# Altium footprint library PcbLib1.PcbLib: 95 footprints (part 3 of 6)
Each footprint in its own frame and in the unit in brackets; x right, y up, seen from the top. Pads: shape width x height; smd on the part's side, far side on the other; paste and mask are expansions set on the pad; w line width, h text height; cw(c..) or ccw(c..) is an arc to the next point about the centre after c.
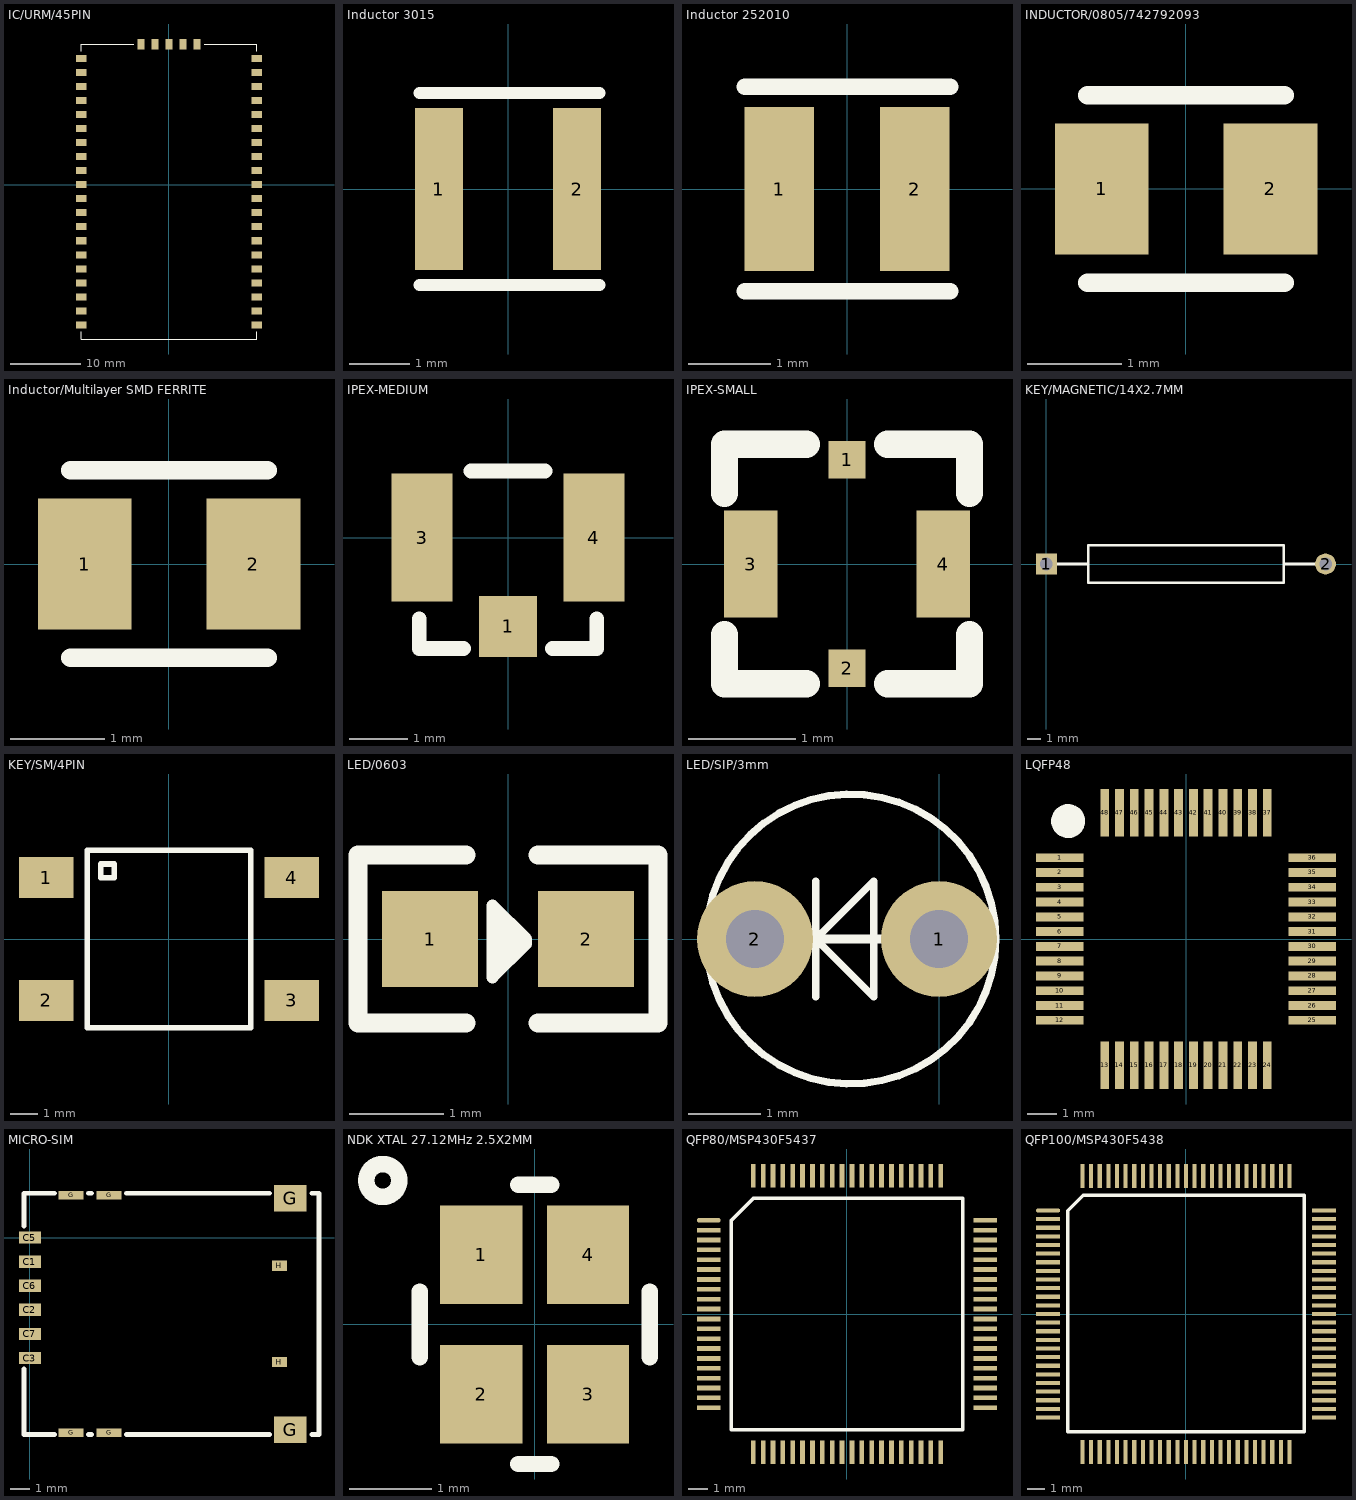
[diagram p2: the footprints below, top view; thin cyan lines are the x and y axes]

## IC/URM/45PIN [mm]
pads (45):
  rect 1.5x1 smd: 1(-12.5,18) 2(-12.5,16) 3(-12.5,14) 4(-12.5,12) 5(-12.5,10) 6(-12.5,8) 7(-12.5,6) 8(-12.5,4) 9(-12.5,2) 10(-12.5,0) 11(-12.5,-2) 12(-12.5,-4) 13(-12.5,-6) 14(-12.5,-8) 15(-12.5,-10) 16(-12.5,-12) 17(-12.5,-14) 18(-12.5,-16) 19(-12.5,-18) 20(-12.5,-20) 21(12.5,-20) 22(12.5,-18) 23(12.5,-16) 24(12.5,-14) 25(12.5,-12) 26(12.5,-10) 27(12.5,-8) 28(12.5,-6) 29(12.5,-4) 30(12.5,-2) 31(12.5,0) 32(12.5,2) 33(12.5,4) 34(12.5,6) 35(12.5,8) 36(12.5,10) 37(12.5,12) 38(12.5,14) 39(12.5,16) 40(12.5,18)
  rect 1x1.5 smd: 41(-4,20) 42(-2,20) 43(0,20) 44(2,20) 45(4,20)
Top Overlay:
  lines w0.127: -12.5,-21 -12.5,-22 12.5,-22 12.5,-21 ; -12.5,19 -12.5,20 -5,20 ; 5,20 12.5,20 12.5,19

## Inductor 3015 [mm]
pads (2):
  rect 0.8x2.7 smd: 1(-1.15,0) 2(1.15,0)
Top Overlay:
  lines w0.2: -1.473,-1.6 1.527,-1.6 ; -1.473,1.6 1.527,1.6

## Inductor 252010 [mm]
pads (2):
  rect 0.85x2 smd: 1(-0.825,0) 2(0.825,0)
Top Overlay:
  lines w0.2: -1.245,-1.245 1.255,-1.245 ; -1.245,1.245 1.255,1.245

## INDUCTOR/0805/742792093 [mm]
pads (2):
  rect 1x1.4 smd paste+0 mask+0.1: 1(-0.9,0) 2(0.9,0)
Top Overlay:
  lines w0.2: -1.05,-1 1.05,-1 ; -1.05,1 1.05,1

## Inductor/Multilayer SMD FERRITE [mm]
pads (2):
  rect 1x1.4 smd paste+0 mask+0.1: 1(-0.9,0) 2(0.9,0)
Top Overlay:
  lines w0.2: -1.05,-1 1.05,-1 ; -1.05,1 1.05,1

## IPEX-MEDIUM [mm]
pads (3):
  rect 1x1.05 smd: 1(0,-1.525)
  rect 1.05x2.2 smd: 3(-1.475,0) 4(1.475,0)
Top Overlay:
  lines w0.254: -1.524,-1.397 -1.524,-1.905 -0.762,-1.905 ; -0.635,1.143 0.635,1.143 ; 0.762,-1.905 1.524,-1.905 1.524,-1.397

## IPEX-SMALL [mm]
pads (4):
  rect 0.35x0.35 smd: 1(0,0.975) 2(0,-0.975)
  rect 0.5x1 smd: 3(-0.9,0) 4(0.9,0)
Top Overlay:
  lines w0.254: -1.143,-0.66 -1.143,-1.118 -0.381,-1.118 ; -1.143,0.66 -1.143,1.118 -0.381,1.118 ; 0.381,-1.118 1.143,-1.118 1.143,-0.66 ; 0.381,1.118 1.143,1.118 1.143,0.66

## KEY/MAGNETIC/14X2.7MM [mm]
pads (2):
  rect 1.5x1.5 hole 0.9: 1(0,0)
  round 1.5 hole 0.9: 2(20,0)
Top Overlay:
  lines w0.2: 0,0 3,0 ; 20,0 17,0 ; 3,0 3,-1.35 17,-1.35 17,0 ; 3,0 3,1.35 17,1.35 17,0

## KEY/SM/4PIN [mm]
pads (4):
  rect 2x1.5 smd: 1(-4.5,2.25) 2(-4.5,-2.25) 3(4.5,-2.25) 4(4.5,2.25)
Top Overlay:
  lines w0.203: -3,-3.25 -3,3.25 3,3.25 3,-3.25 -3,-3.25 ; -2.5,2.25 -2,2.25 -2,2.75 -2.5,2.75 -2.5,2.25

## LED/0603 [mil]
pads (2):
  rect 40x40 smd: 1(-32.5,0) 2(32.5,0)
Top Overlay:
  lines w5: -3.5,-8 -3.5,11 -6.5,14 ; -0.5,-5 -0.5,3 ; -0.5,-3 2.5,0 7.5,0 ; -6.5,14 7.5,0 ; -6.5,14 -6.5,-16 7.5,-2 7.5,0
  lines w8: -17.5,-35 -62.5,-35 -62.5,35 -17.5,35 ; 12.5,-35 62.5,-35 62.5,35 12.5,35

## LED/SIP/3mm [mm]
pads (2):
  round 1.6 hole 0.8: 1(0,0) 2(-2.54,0)
Top Overlay:
  circle w0.1: c-1.216,0 r2
  lines w0.1: -1.7,-0.8 -1.7,0 ; -1.7,0.8 -1.7,0 ; -1.7,0 -0.9,0.8 -0.9,-0.8 -1.7,0
  lines w0.127: -1.7,0 -0.686,0

## LQFP48 [mm]
pads (48):
  rect 1.6x0.3 smd paste+0 mask+0.04: 1(-4.275,2.75) 2(-4.275,2.25) 3(-4.275,1.75) 4(-4.275,1.25) 5(-4.275,0.75) 6(-4.275,0.25) 7(-4.275,-0.25) 8(-4.275,-0.75) 9(-4.275,-1.25) 10(-4.275,-1.75) 11(-4.275,-2.25) 12(-4.275,-2.75) 25(4.275,-2.75) 26(4.275,-2.25) 27(4.275,-1.75) 28(4.275,-1.25) 29(4.275,-0.75) 30(4.275,-0.25) 31(4.275,0.25) 32(4.275,0.75) 33(4.275,1.25) 34(4.275,1.75) 35(4.275,2.25) 36(4.275,2.75)
  rect 0.3x1.6 smd paste+0 mask+0.04: 13(-2.75,-4.275) 14(-2.25,-4.275) 15(-1.75,-4.275) 16(-1.25,-4.275) 17(-0.75,-4.275) 18(-0.25,-4.275) 19(0.25,-4.275) 20(0.75,-4.275) 21(1.25,-4.275) 22(1.75,-4.275) 23(2.25,-4.275) 24(2.75,-4.275) 37(2.75,4.275) 38(2.25,4.275) 39(1.75,4.275) 40(1.25,4.275) 41(0.75,4.275) 42(0.25,4.275) 43(-0.25,4.275) 44(-0.75,4.275) 45(-1.25,4.275) 46(-1.75,4.275) 47(-2.25,4.275) 48(-2.75,4.275)
Top Overlay:
  circle w0.6: c-3.988,3.988 r0.274

## MICRO-SIM [mm]
pads (14):
  rect 1.15x0.65 smd: C1(0,-1.27) C2(0,-3.81) C3(0,-6.35) C5(0,0) C6(0,-2.54) C7(0,-5.08)
  rect 1.3x0.45 smd: G(2.17,-10.295) G(2.17,2.235) G(4.17,-10.295) G(4.17,2.235)
  rect 1.7x1.4 smd: G(13.73,-10.135) G(13.73,2.075)
  rect 0.8x0.54 smd: H(13.15,-6.565) H(13.15,-1.485)
Top Overlay:
  lines w0.254: -0.305,-6.934 -0.305,-10.389 1.295,-10.389 ; -0.305,0.61 -0.305,2.337 1.295,2.337 ; 3.073,2.337 3.251,2.337 ; 3.086,-10.389 3.264,-10.389 ; 5.08,-10.389 12.624,-10.389 ; 5.08,2.337 12.624,2.337 ; 14.859,-10.389 15.24,-10.389 15.24,2.337 14.859,2.337

## NDK XTAL 27.12MHz 2.5X2MM [mm]
pads (4):
  rect 1x1.2 smd paste+0 mask+0.1: 1(-0.65,0.85) 3(0.65,-0.85) 4(0.65,0.85)
  rect 1x1.2 smd mask+0.1: 2(-0.65,-0.85)
Top Overlay:
  lines w0.2: -1.4,-0.4 -1.4,0.4 ; -0.2,-1.7 0.2,-1.7 ; -0.2,1.7 0.2,1.7 ; 1.4,-0.4 1.4,0.4 ; -2.049,1.752 -2.049,1.766 -2.047,1.78 -2.045,1.794 -2.041,1.808 -2.037,1.821 -2.032,1.834 -2.026,1.846 -2.019,1.858 -2.011,1.87 -2.002,1.881 -1.993,1.891 -1.983,1.901 -1.972,1.91 -1.961,1.918 -1.949,1.926 -1.937,1.932 -1.924,1.938 -1.911,1.943 -1.898,1.947 -1.884,1.949 -1.87,1.951 -1.856,1.952 -1.842,1.952 -1.828,1.951 -1.814,1.949 -1.801,1.947 -1.787,1.943 -1.774,1.938 -1.761,1.932 -1.749,1.926 -1.737,1.918 -1.726,1.91 -1.715,1.901 -1.705,1.891 -1.696,1.881 -1.687,1.87 -1.68,1.858 -1.673,1.846 -1.666,1.834 -1.661,1.821 -1.657,1.808 -1.654,1.794 -1.651,1.78 -1.65,1.766 -1.649,1.752 -1.65,1.738 -1.651,1.725 -1.654,1.711 -1.657,1.697 -1.661,1.684 -1.666,1.671 -1.673,1.659 -1.68,1.646 -1.687,1.635 -1.696,1.624 -1.705,1.614 -1.715,1.604 -1.726,1.595 -1.737,1.587 -1.749,1.579 -1.761,1.573 -1.774,1.567 -1.787,1.562 -1.801,1.558 -1.814,1.555 -1.828,1.554 -1.842,1.553 -1.856,1.553 -1.87,1.554 -1.884,1.555 -1.898,1.558 -1.911,1.562 -1.924,1.567 -1.937,1.573 -1.949,1.579 -1.961,1.587 -1.972,1.595 -1.983,1.604 -1.993,1.614 -2.002,1.624 -2.011,1.635 -2.019,1.646 -2.026,1.659 -2.032,1.671 -2.037,1.684 -2.041,1.697 -2.045,1.711 -2.047,1.725 -2.049,1.738 -2.049,1.752

## QFP80/MSP430F5437 [mm]
pads (80):
  oval 1.2x0.24 smd: 1(-7,4.75)
  rect 1.2x0.24 smd: 2(-7,4.25) 3(-7,3.75) 4(-7,3.25) 5(-7,2.75) 6(-7,2.25) 7(-7,1.75) 8(-7,1.25) 9(-7,0.75) 10(-7,0.25) 11(-7,-0.25) 12(-7,-0.75) 13(-7,-1.25) 14(-7,-1.75) 15(-7,-2.25) 16(-7,-2.75) 17(-7,-3.25) 18(-7,-3.75) 19(-7,-4.25) 20(-7,-4.75) 41(7,-4.75) 42(7,-4.25) 43(7,-3.75) 44(7,-3.25) 45(7,-2.75) 46(7,-2.25) 47(7,-1.75) 48(7,-1.25) 49(7,-0.75) 50(7,-0.25) 51(7,0.25) 52(7,0.75) 53(7,1.25) 54(7,1.75) 55(7,2.25) 56(7,2.75) 57(7,3.25) 58(7,3.75) 59(7,4.25) 60(7,4.75)
  rect 0.24x1.2 smd: 21(-4.75,-7) 22(-4.25,-7) 23(-3.75,-7) 24(-3.25,-7) 25(-2.75,-7) 26(-2.25,-7) 27(-1.75,-7) 28(-1.25,-7) 29(-0.75,-7) 30(-0.25,-7) 31(0.25,-7) 32(0.75,-7) 33(1.25,-7) 34(1.75,-7) 35(2.25,-7) 36(2.75,-7) 37(3.25,-7) 38(3.75,-7) 39(4.25,-7) 40(4.75,-7) 61(4.75,7) 62(4.25,7) 63(3.75,7) 64(3.25,7) 65(2.75,7) 66(2.25,7) 67(1.75,7) 68(1.25,7) 69(0.75,7) 70(0.25,7) 71(-0.25,7) 72(-0.75,7) 73(-1.25,7) 74(-1.75,7) 75(-2.25,7) 76(-2.75,7) 77(-3.25,7) 78(-3.75,7) 79(-4.25,7) 80(-4.75,7)
Top Overlay:
  lines w0.2: -5.865,-5.865 -5.865,4.73 -4.73,5.865 5.865,5.865 5.865,-5.865 -5.865,-5.865

## QFP100/MSP430F5438 [mm]
pads (100):
  oval 1.4x0.24 smd: 1(-8,6)
  rect 1.4x0.24 smd: 2(-8,5.5) 3(-8,5) 4(-8,4.5) 5(-8,4) 6(-8,3.5) 7(-8,3) 8(-8,2.5) 9(-8,2) 10(-8,1.5) 11(-8,1) 12(-8,0.5) 13(-8,0) 14(-8,-0.5) 15(-8,-1) 16(-8,-1.5) 17(-8,-2) 18(-8,-2.5) 19(-8,-3) 20(-8,-3.5) 21(-8,-4) 22(-8,-4.5) 23(-8,-5) 24(-8,-5.5) 25(-8,-6) 51(8,-6) 52(8,-5.5) 53(8,-5) 54(8,-4.5) 55(8,-4) 56(8,-3.5) 57(8,-3) 58(8,-2.5) 59(8,-2) 60(8,-1.5) 61(8,-1) 62(8,-0.5) 63(8,0) 64(8,0.5) 65(8,1) 66(8,1.5) 67(8,2) 68(8,2.5) 69(8,3) 70(8,3.5) 71(8,4) 72(8,4.5) 73(8,5) 74(8,5.5) 75(8,6)
  rect 0.24x1.4 smd: 26(-6,-8) 27(-5.5,-8) 28(-5,-8) 29(-4.5,-8) 30(-4,-8) 31(-3.5,-8) 32(-3,-8) 33(-2.5,-8) 34(-2,-8) 35(-1.5,-8) 36(-1,-8) 37(-0.5,-8) 38(0,-8) 39(0.5,-8) 40(1,-8) 41(1.5,-8) 42(2,-8) 43(2.5,-8) 44(3,-8) 45(3.5,-8) 46(4,-8) 47(4.5,-8) 48(5,-8) 49(5.5,-8) 50(6,-8) 76(6,8) 77(5.5,8) 78(5,8) 79(4.5,8) 80(4,8) 81(3.5,8) 82(3,8) 83(2.5,8) 84(2,8) 85(1.5,8) 86(1,8) 87(0.5,8) 88(0,8) 89(-0.5,8) 90(-1,8) 91(-1.5,8) 92(-2,8) 93(-2.5,8) 94(-3,8) 95(-3.5,8) 96(-4,8) 97(-4.5,8) 98(-5,8) 99(-5.5,8) 100(-6,8)
Top Overlay:
  lines w0.2: -6.857,-6.827 -6.857,6 -5.968,6.889 6.859,6.889 6.859,-6.827 -6.857,-6.827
